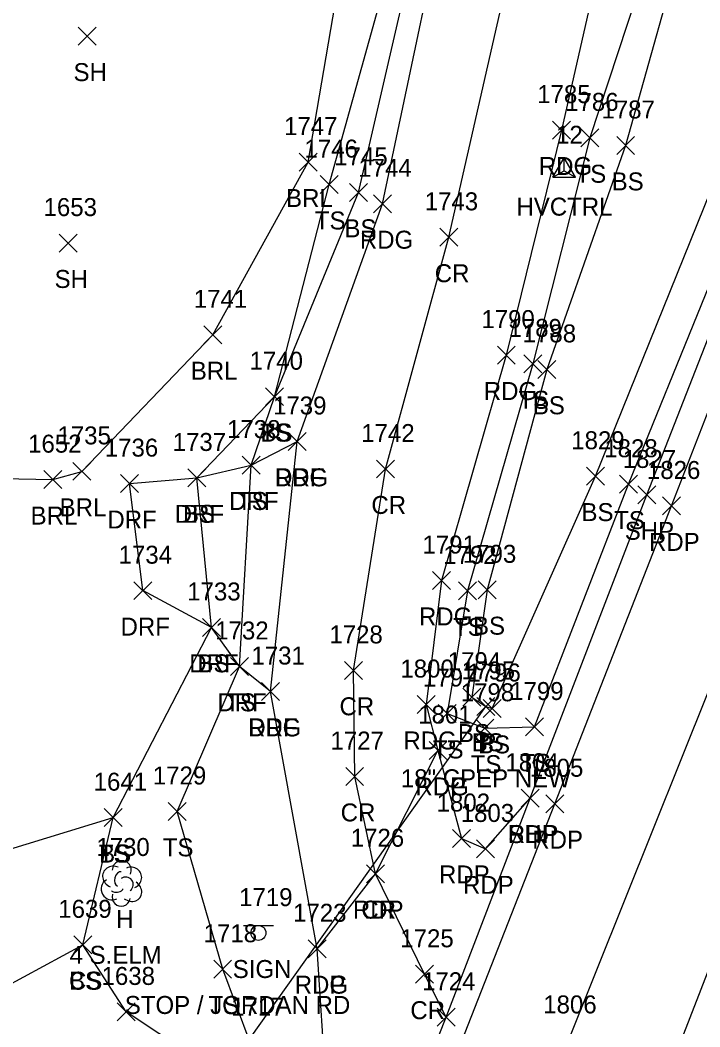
# Model space of a CAD drawing. Extents: x 1554917 to 1555870, y 813367 to 816333.
# Drawn here: x 1555214.2 to 1555289.9, y 814161.6 to 814273.6 of the extents above; entities that cross this region are included whole.
import ezdxf

# ---------------------------------------------------------------- set-up
doc = ezdxf.new("R2010")
doc.units = 0
for name, color, linetype in [('C_A', 7, 'Continuous'), ('C_I', 7, 'Continuous'), ('CPSM', 7, 'Continuous'), ('D_A', 7, 'Continuous'), ('D_C', 7, 'Continuous'), ('D_I', 7, 'Continuous'), ('D_TIC', 7, 'Continuous'), ('DCP', 7, 'Continuous'), ('L_A', 7, 'Continuous'), ('L_C', 7, 'Continuous'), ('L_I', 7, 'Continuous'), ('L_TIC', 7, 'Continuous'), ('LABL', 7, 'Continuous'), ('LELB', 7, 'Continuous'), ('LTD', 7, 'Continuous'), ('P_A', 7, 'Continuous'), ('P_I', 7, 'Continuous'), ('P_TIC', 7, 'Continuous'), ('PET', 7, 'Continuous'), ('PEU', 7, 'Continuous'), ('PRC', 7, 'Continuous'), ('PSP', 7, 'Continuous'), ('R_A', 7, 'Continuous'), ('R_I', 7, 'Continuous'), ('R_TIC', 7, 'Continuous'), ('RDF', 7, 'Continuous'), ('S_A', 7, 'Continuous'), ('S_C', 7, 'Continuous'), ('S_I', 7, 'Continuous'), ('SSGN', 7, 'Continuous')]:
    doc.layers.add(name, color=color, linetype=linetype)

msp = doc.modelspace()

# ---------------------------------------------------------------- linework, layer by layer
at = {"layer": 'CPSM'}
for p, q in [((1555273.51, 814256.16), (1555274.76, 814258.33)), ((1555276.01, 814256.16), (1555274.76, 814258.33)), ((1555274.76, 814256.88), (1555274.76, 814258.33)), ((1555273.51, 814256.16), (1555274.76, 814256.88)), ((1555274.76, 814256.88), (1555274.76, 814256.88)), ((1555274.76, 814256.88), (1555276.01, 814256.16)), ((1555273.51, 814256.16), (1555276.01, 814256.16))]:
    msp.add_line(p, q, dxfattribs=at)
at = {"layer": 'D_TIC'}
for points in [[(1555265.03, 814196.26), (1555267.03, 814198.26)], [(1555267.03, 814196.26), (1555265.03, 814198.26)]]:
    msp.add_lwpolyline(points, dxfattribs=at)
at = {"layer": 'DCP'}
msp.add_lwpolyline([(1555236.77, 814156.09), (1555266.03, 814197.26)], dxfattribs=at)
at = {"layer": 'L_TIC'}
for points in [[(1555220.63, 814270.85), (1555222.63, 814272.85)], [(1555222.63, 814270.85), (1555220.63, 814272.85)], [(1555276.62, 814259.54), (1555278.62, 814261.54)], [(1555278.62, 814259.54), (1555276.62, 814261.54)], [(1555280.61, 814258.69), (1555282.61, 814260.69)], [(1555282.61, 814258.69), (1555280.61, 814260.69)], [(1555245.25, 814256.84), (1555247.25, 814258.84)], [(1555247.25, 814256.84), (1555245.25, 814258.84)], [(1555247.59, 814254.34), (1555249.59, 814256.34)], [(1555249.59, 814254.34), (1555247.59, 814256.34)], [(1555250.85, 814253.47), (1555252.85, 814255.47)], [(1555252.85, 814253.47), (1555250.85, 814255.47)], [(1555218.52, 814247.83), (1555220.52, 814249.83)], [(1555220.52, 814247.83), (1555218.52, 814249.83)], [(1555234.64, 814237.62), (1555236.64, 814239.62)], [(1555236.64, 814237.62), (1555234.64, 814239.62)], [(1555270.26, 814234.38), (1555272.26, 814236.38)], [(1555272.26, 814234.38), (1555270.26, 814236.38)], [(1555271.83, 814233.77), (1555273.83, 814235.77)], [(1555273.83, 814233.77), (1555271.83, 814235.77)], [(1555241.5, 814230.73), (1555243.5, 814232.73)], [(1555243.5, 814230.73), (1555241.5, 814232.73)], [(1555241.5, 814230.73), (1555243.5, 814232.73)], [(1555243.5, 814230.73), (1555241.5, 814232.73)], [(1555238.91, 814223.12), (1555240.91, 814225.12)], [(1555240.91, 814223.12), (1555238.91, 814225.12)], [(1555220.03, 814222.42), (1555222.03, 814224.42)], [(1555222.03, 814222.42), (1555220.03, 814224.42)], [(1555277.25, 814221.88), (1555279.25, 814223.88)], [(1555279.25, 814221.88), (1555277.25, 814223.88)], [(1555216.8, 814221.5), (1555218.8, 814223.5)], [(1555218.8, 814221.5), (1555216.8, 814223.5)], [(1555232.86, 814221.69), (1555234.86, 814223.69)], [(1555234.86, 814221.69), (1555232.86, 814223.69)], [(1555280.92, 814220.99), (1555282.92, 814222.99)], [(1555282.92, 814220.99), (1555280.92, 814222.99)], [(1555262.98, 814209.11), (1555264.98, 814211.11)], [(1555264.98, 814209.11), (1555262.98, 814211.11)], [(1555265.17, 814209.24), (1555267.17, 814211.24)], [(1555267.17, 814209.24), (1555265.17, 814211.24)], [(1555234.48, 814205.05), (1555236.48, 814207.05)], [(1555236.48, 814205.05), (1555234.48, 814207.05)], [(1555237.6, 814200.71), (1555239.6, 814202.71)], [(1555239.6, 814200.71), (1555237.6, 814202.71)], [(1555263.49, 814197.29), (1555265.49, 814199.29)], [(1555265.49, 814197.29), (1555263.49, 814199.29)], [(1555265.03, 814196.26), (1555267.03, 814198.26)], [(1555267.03, 814196.26), (1555265.03, 814198.26)], [(1555260.73, 814195.47), (1555262.73, 814197.47)], [(1555262.73, 814195.47), (1555260.73, 814197.47)], [(1555265.73, 814196.03), (1555267.73, 814198.03)], [(1555267.73, 814196.03), (1555265.73, 814198.03)], [(1555270.45, 814193.97), (1555272.45, 814195.97)], [(1555272.45, 814193.97), (1555270.45, 814195.97)], [(1555264.94, 814193.83), (1555266.94, 814195.83)], [(1555266.94, 814193.83), (1555264.94, 814195.83)], [(1555223.53, 814183.88), (1555225.53, 814185.88)], [(1555225.53, 814183.88), (1555223.53, 814185.88)], [(1555223.53, 814183.88), (1555225.53, 814185.88)], [(1555225.53, 814183.88), (1555223.53, 814185.88)], [(1555230.65, 814184.57), (1555232.65, 814186.57)], [(1555232.65, 814184.57), (1555230.65, 814186.57)], [(1555220.17, 814169.73), (1555222.17, 814171.73)], [(1555222.17, 814169.73), (1555220.17, 814171.73)], [(1555220.17, 814169.73), (1555222.17, 814171.73)], [(1555222.17, 814169.73), (1555220.17, 814171.73)], [(1555235.73, 814167.01), (1555237.73, 814169.01)], [(1555237.73, 814167.01), (1555235.73, 814169.01)], [(1555224.98, 814162.26), (1555226.98, 814164.26)], [(1555226.98, 814162.26), (1555224.98, 814164.26)]]:
    msp.add_lwpolyline(points, dxfattribs=at)
at = {"layer": 'LABL'}
msp.add_lwpolyline([(1555170.56, 814225.07), (1555196.9, 814222.93), (1555217.8, 814222.5), (1555221.03, 814223.42), (1555235.64, 814238.62), (1555246.25, 814257.84), (1555251.52, 814288.71), (1555259.39, 814330.22), (1555249.41, 814332.16)], dxfattribs=at)
at = {"layer": 'LELB'}
for points in [[(1555296.24, 814366.8), (1555290.72, 814331.05), (1555289.09, 814310.79), (1555285.93, 814285.82), (1555277.62, 814260.54), (1555271.26, 814235.38), (1555263.98, 814210.11), (1555261.73, 814196.47), (1555265.94, 814194.83), (1555271.45, 814194.97), (1555281.92, 814221.99), (1555299.07, 814264.14), (1555315.35, 814304.52), (1555325.95, 814332.17)], [(1555236.77, 814156.09), (1555225.98, 814163.26), (1555221.17, 814170.73), (1555224.53, 814184.88), (1555235.48, 814206.05), (1555233.86, 814222.69), (1555242.5, 814231.73), (1555251.85, 814254.47), (1555261.04, 814294.17), (1555268.16, 814328.27), (1555269.68, 814335.29), (1555272.72, 814341.69)], [(1555161.57, 813925.65), (1555168.92, 813938.89), (1555173.57, 813945.95), (1555174.16, 813952.01), (1555182.4, 813974.26), (1555190.04, 813992.11), (1555201.74, 814019.14), (1555212.19, 814045.46), (1555215.96, 814054.45), (1555221.93, 814072.78), (1555233.01, 814105.58), (1555244.12, 814126.91), (1555239.17, 814141.42), (1555241.48, 814149.75), (1555239.8, 814159.84), (1555236.73, 814168.01), (1555231.65, 814185.57), (1555238.6, 814201.71), (1555239.91, 814224.12), (1555242.5, 814231.73), (1555248.59, 814255.34), (1555259.33, 814293.88), (1555265.42, 814329.58), (1555267.14, 814335.72)], [(1555288.75, 814285.24), (1555281.61, 814259.69), (1555272.83, 814234.77), (1555266.17, 814210.24), (1555264.49, 814198.29), (1555266.03, 814197.26), (1555266.73, 814197.03), (1555278.25, 814222.88), (1555295.68, 814265.95), (1555300.44, 814279.31)], [(1555172.7, 814171.33), (1555195.77, 814173.65), (1555207.42, 814179.65), (1555224.53, 814184.88)], [(1555103.83, 814081.29), (1555127.34, 814087.63), (1555145.8, 814111.67), (1555155.27, 814142.44), (1555178.24, 814154.02), (1555199.22, 814158.86), (1555221.17, 814170.73)]]:
    msp.add_lwpolyline(points, dxfattribs=at)
at = {"layer": 'LTD'}
msp.add_line((1555225.44, 814177.61), (1555225.44, 814177.61), dxfattribs=at)
msp.add_line((1555225.44, 814177.61), (1555225.44, 814177.61), dxfattribs=at)
msp.add_arc((1555225.49, 814179.04), 1.05, 335.5272, 180.9563, dxfattribs=at)
for centre, major_axis, ratio, start_param, end_param in [((1555224.65, 814178.27), (1.21, -0.51), 0.895232, 1.570796, 4.712389), ((1555226.48, 814178.19), (-1.14, -0.48), 0.949671, 1.570796, 4.712389), ((1555224.36, 814176.9), (0.58, -1.04), 0.959034, 3.141593, 6.283185), ((1555225.23, 814178.06), (-0.208, -0.792), 0.645439, 3.141593, 6.283185), ((1555225.94, 814177.44), (-0.5, 0.667), 0.989748, 3.141593, 6.283185), ((1555224.98, 814176.86), (-0.625, -0.083), 0.423636, 0, 3.141593), ((1555226.44, 814176.77), (-1.09, 0.79), 0.841452, 1.570796, 4.712389), ((1555225.44, 814176.11), (0.26, 1.06), 0.942809, 1.570796, 4.712389)]:
    msp.add_ellipse(centre, major_axis=major_axis, ratio=ratio, start_param=start_param, end_param=end_param, dxfattribs=at)
at = {"layer": 'P_TIC'}
for points in [[(1555273.45, 814260.4), (1555275.45, 814262.4)], [(1555275.45, 814260.4), (1555273.45, 814262.4)], [(1555253.52, 814252.2), (1555255.52, 814254.2)], [(1555255.52, 814252.2), (1555253.52, 814254.2)], [(1555260.92, 814248.47), (1555262.92, 814250.47)], [(1555262.92, 814248.47), (1555260.92, 814250.47)], [(1555267.32, 814235.36), (1555269.32, 814237.36)], [(1555269.32, 814235.36), (1555267.32, 814237.36)], [(1555244.04, 814225.75), (1555246.04, 814227.75)], [(1555246.04, 814225.75), (1555244.04, 814227.75)], [(1555253.86, 814222.68), (1555255.86, 814224.68)], [(1555255.86, 814222.68), (1555253.86, 814224.68)], [(1555282.98, 814219.8), (1555284.98, 814221.8)], [(1555284.98, 814219.8), (1555282.98, 814221.8)], [(1555285.72, 814218.57), (1555287.72, 814220.57)], [(1555287.72, 814218.57), (1555285.72, 814220.57)], [(1555260.1, 814210.27), (1555262.1, 814212.27)], [(1555262.1, 814210.27), (1555260.1, 814212.27)], [(1555250.3, 814200.27), (1555252.3, 814202.27)], [(1555252.3, 814200.27), (1555250.3, 814202.27)], [(1555241.05, 814197.92), (1555243.05, 814199.92)], [(1555243.05, 814197.92), (1555241.05, 814199.92)], [(1555258.38, 814196.47), (1555260.38, 814198.47)], [(1555260.38, 814196.47), (1555258.38, 814198.47)], [(1555259.71, 814191.35), (1555261.71, 814193.35)], [(1555261.71, 814191.35), (1555259.71, 814193.35)], [(1555259.71, 814191.35), (1555261.71, 814193.35)], [(1555261.71, 814191.35), (1555259.71, 814193.35)], [(1555250.43, 814188.46), (1555252.43, 814190.46)], [(1555252.43, 814188.46), (1555250.43, 814190.46)], [(1555269.99, 814186.05), (1555271.99, 814188.05)], [(1555271.99, 814186.05), (1555269.99, 814188.05)], [(1555269.99, 814186.05), (1555271.99, 814188.05)], [(1555271.99, 814186.05), (1555269.99, 814188.05)], [(1555272.72, 814185.43), (1555274.72, 814187.43)], [(1555274.72, 814185.43), (1555272.72, 814187.43)], [(1555262.33, 814181.56), (1555264.33, 814183.56)], [(1555264.33, 814181.56), (1555262.33, 814183.56)], [(1555265.01, 814180.4), (1555267.01, 814182.4)], [(1555267.01, 814180.4), (1555265.01, 814182.4)], [(1555252.74, 814177.64), (1555254.74, 814179.64)], [(1555254.74, 814177.64), (1555252.74, 814179.64)], [(1555252.74, 814177.64), (1555254.74, 814179.64)], [(1555254.74, 814177.64), (1555252.74, 814179.64)], [(1555246.26, 814169.29), (1555248.26, 814171.29)], [(1555248.26, 814169.29), (1555246.26, 814171.29)], [(1555246.26, 814169.29), (1555248.26, 814171.29)], [(1555248.26, 814169.29), (1555246.26, 814171.29)], [(1555258.2, 814166.45), (1555260.2, 814168.45)], [(1555260.2, 814166.45), (1555258.2, 814168.45)], [(1555260.62, 814161.67), (1555262.62, 814163.67)], [(1555262.62, 814161.67), (1555260.62, 814163.67)], [(1555260.62, 814161.67), (1555262.62, 814163.67)], [(1555262.62, 814161.67), (1555260.62, 814163.67)]]:
    msp.add_lwpolyline(points, dxfattribs=at)
at = {"layer": 'PET'}
for points in [[(1555161.36, 813900.53), (1555183.5, 813956.99), (1555189.63, 813971.7), (1555196.36, 813987.75), (1555203.89, 814008), (1555206.01, 814012.95), (1555218.07, 814043.52), (1555227.32, 814068.19), (1555240.79, 814103.21), (1555254.41, 814137.22), (1555273.72, 814186.43), (1555286.72, 814219.57), (1555303.34, 814262.32), (1555319.11, 814302.56), (1555330.34, 814331.97)], [(1555182.57, 813892.25), (1555203.7, 813945.01), (1555216.85, 813978.34), (1555228.72, 814008.85), (1555239.47, 814035.47), (1555248.64, 814059.88), (1555262.92, 814096.01), (1555276.68, 814131.3), (1555286.36, 814156.33), (1555297.11, 814184.04), (1555306.67, 814209.51), (1555324.28, 814253.26), (1555340.35, 814293.54), (1555352.6, 814325.05)], [(1555248.96, 814130.73), (1555248.65, 814139.98), (1555248.27, 814154.83), (1555247.26, 814170.29), (1555253.74, 814178.64), (1555260.71, 814192.35), (1555263.33, 814182.56), (1555266.01, 814181.4), (1555270.99, 814187.05)]]:
    msp.add_lwpolyline(points, dxfattribs=at)
at = {"layer": 'PEU'}
for points in [[(1555247.26, 814170.29), (1555242.05, 814198.92), (1555245.04, 814226.75), (1555254.52, 814253.2), (1555263.19, 814294.17), (1555270.38, 814328.05), (1555270.98, 814335.52), (1555272.72, 814341.69), (1555275.54, 814362.57), (1555278.04, 814372.88)], [(1555294.23, 814367.85), (1555287.98, 814331.7), (1555283.95, 814310.99), (1555280.12, 814286.26), (1555274.45, 814261.4), (1555268.32, 814236.36), (1555261.1, 814211.27), (1555259.38, 814197.47), (1555260.71, 814192.35)]]:
    msp.add_lwpolyline(points, dxfattribs=at)
at = {"layer": 'PRC'}
for points in [[(1555261.62, 814162.67), (1555259.2, 814167.45), (1555253.74, 814178.64), (1555251.43, 814189.46), (1555251.3, 814201.27), (1555254.86, 814223.68), (1555261.92, 814249.47), (1555271.63, 814292.21), (1555278.12, 814326.56), (1555280.66, 814350.27), (1555285.82, 814371.24)], [(1554976.76, 813382.18), (1554992.84, 813427.9), (1555014.07, 813486.01), (1555030.62, 813532.31), (1555046.37, 813573.08), (1555064.69, 813621.19), (1555082.41, 813667.53), (1555112.1, 813744.1), (1555110.69, 813739.79), (1555136.16, 813805.74), (1555152.52, 813846.93), (1555172.03, 813896.18), (1555193.96, 813951.2), (1555206.37, 813983.4), (1555218.13, 814013.22), (1555228.65, 814039.26), (1555237.93, 814064.31), (1555252.22, 814099.76), (1555265.8, 814135.89), (1555275.26, 814160.09), (1555297.17, 814214.77), (1555313.83, 814257.94), (1555329.72, 814298.26), (1555342.03, 814329.92)]]:
    msp.add_lwpolyline(points, dxfattribs=at)
at = {"layer": 'PSP'}
msp.add_lwpolyline([(1555160.79, 813906.47), (1555173.05, 813937.33), (1555179.42, 813953.63), (1555181.24, 813957.84), (1555186.72, 813973.16), (1555194.02, 813990.9), (1555204.38, 814016.29), (1555205.03, 814017.75), (1555215.29, 814044.5), (1555224.66, 814068.93), (1555238.68, 814103.48), (1555248.96, 814130.73), (1555261.62, 814162.67), (1555270.99, 814187.05), (1555283.98, 814220.8), (1555300.65, 814263.34), (1555316.51, 814303.51), (1555327.36, 814331.38)], dxfattribs=at)
at = {"layer": 'R_TIC'}
for points in [[(1555244.04, 814225.75), (1555246.04, 814227.75)], [(1555246.04, 814225.75), (1555244.04, 814227.75)], [(1555238.91, 814223.12), (1555240.91, 814225.12)], [(1555240.91, 814223.12), (1555238.91, 814225.12)], [(1555225.35, 814221.06), (1555227.35, 814223.06)], [(1555227.35, 814221.06), (1555225.35, 814223.06)], [(1555232.86, 814221.69), (1555234.86, 814223.69)], [(1555234.86, 814221.69), (1555232.86, 814223.69)], [(1555226.83, 814209.14), (1555228.83, 814211.14)], [(1555228.83, 814209.14), (1555226.83, 814211.14)], [(1555234.48, 814205.05), (1555236.48, 814207.05)], [(1555236.48, 814205.05), (1555234.48, 814207.05)], [(1555237.6, 814200.71), (1555239.6, 814202.71)], [(1555239.6, 814200.71), (1555237.6, 814202.71)], [(1555241.05, 814197.92), (1555243.05, 814199.92)], [(1555243.05, 814197.92), (1555241.05, 814199.92)]]:
    msp.add_lwpolyline(points, dxfattribs=at)
at = {"layer": 'RDF'}
msp.add_lwpolyline([(1555242.05, 814198.92), (1555238.6, 814201.71), (1555235.48, 814206.05), (1555227.83, 814210.14), (1555226.35, 814222.06), (1555233.86, 814222.69), (1555239.91, 814224.12), (1555245.04, 814226.75)], dxfattribs=at)
at = {"layer": 'SSGN'}
for p, q in [((1555239.06, 814172.89), (1555242.4, 814172.89)), ((1555240.71, 814172.05), (1555240.71, 814172.05))]:
    msp.add_line(p, q, dxfattribs=at)
msp.add_circle((1555240.71, 814172.05), 0.833, dxfattribs=at)

# ---------------------------------------------------------------- texts
at = {"layer": 'C_A'}
msp.add_text('HVCTRL', height=2, dxfattribs=at).set_placement((1555269.45, 814251.88))
at = {"layer": 'C_I'}
msp.add_text('12', height=2, dxfattribs=at).set_placement((1555273.86, 814259.88))
at = {"layer": 'D_A'}
msp.add_text('P', height=2, dxfattribs=at).set_placement((1555265.41, 814192.26))
at = {"layer": 'D_C'}
msp.add_text('18" CPEP NEW', height=2, dxfattribs=at).set_placement((1555256.57, 814188.26))
at = {"layer": 'D_I'}
msp.add_text('1795', height=2, dxfattribs=at).set_placement((1555263.34, 814200.26))
at = {"layer": 'L_A'}
for s, p in [('SH', (1555220.12, 814266.85)), ('TS', (1555276.03, 814255.54)), ('BS', (1555280.05, 814254.69)), ('BRL', (1555243.79, 814252.84)), ('TS', (1555247, 814250.34)), ('BS', (1555250.29, 814249.47)), ('SH', (1555218.01, 814243.83)), ('BRL', (1555233.18, 814233.62)), ('TS', (1555269.67, 814230.38)), ('BS', (1555271.27, 814229.77)), ('TS', (1555240.91, 814226.73)), ('BS', (1555240.94, 814226.73)), ('TS', (1555238.32, 814219.12)), ('BRL', (1555215.34, 814217.5)), ('BRL', (1555218.57, 814218.42)), ('BS', (1555232.3, 814217.69)), ('BS', (1555276.69, 814217.88)), ('TS', (1555280.33, 814216.99)), ('TS', (1555262.39, 814205.11)), ('BS', (1555264.61, 814205.24)), ('BS', (1555233.92, 814201.05)), ('TS', (1555237.01, 814196.71)), ('BS', (1555262.93, 814193.29)), ('BS', (1555264.47, 814192.26)), ('BS', (1555265.17, 814192.03)), ('TS', (1555260.14, 814191.47)), ('TS', (1555264.35, 814189.83)), ('TS', (1555269.86, 814189.97)), ('TS', (1555230.06, 814180.57)), ('TS', (1555222.94, 814179.88)), ('BS', (1555222.97, 814179.88)), ('H', (1555224.87, 814172.61)), ('CS', (1555219.61, 814165.73)), ('BS', (1555219.61, 814165.73)), ('TS', (1555235.14, 814163.01))]:
    msp.add_text(s, height=2, dxfattribs=at).set_placement(p)
at = {"layer": 'L_C'}
msp.add_text('4 S.ELM', height=2, dxfattribs=at).set_placement((1555219.68, 814168.61))
at = {"layer": 'L_I'}
for s, p in [('1786', (1555274.87, 814263.54)), ('1787', (1555278.92, 814262.69)), ('1747', (1555243.56, 814260.84)), ('1746', (1555245.84, 814258.34)), ('1745', (1555249.16, 814257.47)), ('1653', (1555216.78, 814251.83)), ('1741', (1555233.51, 814241.62)), ('1789', (1555268.56, 814238.38)), ('1788', (1555270.14, 814237.77)), ('1740', (1555239.72, 814234.73)), ('1740', (1555239.72, 814234.73)), ('1735', (1555218.33, 814226.42)), ('1738', (1555237.22, 814227.12)), ('1652', (1555215.06, 814225.5)), ('1737', (1555231.16, 814225.69)), ('1829', (1555275.55, 814225.88)), ('1828', (1555279.23, 814224.99)), ('1792', (1555261.29, 814213.11)), ('1793', (1555263.48, 814213.24)), ('1733', (1555232.78, 814209.05)), ('1732', (1555235.9, 814204.71)), ('1794', (1555261.79, 814201.29)), ('1797', (1555259.04, 814199.47)), ('1795', (1555263.34, 814200.26)), ('1796', (1555263.98, 814200.03)), ('1798', (1555263.24, 814197.83)), ('1799', (1555268.75, 814197.97)), ('1729', (1555228.95, 814188.57)), ('1641', (1555222.36, 814187.88)), ('1641', (1555222.36, 814187.88)), ('1730', (1555222.66, 814180.61)), ('1639', (1555218.42, 814173.73)), ('1639', (1555218.42, 814173.73)), ('1718', (1555234.61, 814171.01)), ('1638', (1555223.24, 814166.26)), ('1717', (1555237.67, 814162.84))]:
    msp.add_text(s, height=2, dxfattribs=at).set_placement(p)
at = {"layer": 'P_A'}
for s, p in [('RDG', (1555271.94, 814256.4)), ('RDG', (1555252.01, 814248.2)), ('CR', (1555260.35, 814244.47)), ('RDG', (1555265.81, 814231.36)), ('RDG', (1555242.53, 814221.75)), ('CR', (1555253.29, 814218.68)), ('SHP', (1555281.51, 814215.8)), ('RDP', (1555284.21, 814214.57)), ('RDG', (1555258.59, 814206.27)), ('CR', (1555249.74, 814196.27)), ('RDG', (1555239.54, 814193.92)), ('RDG', (1555256.86, 814192.47)), ('RDG', (1555258.2, 814187.35)), ('RDP', (1555258.2, 814187.35)), ('CR', (1555249.87, 814184.46)), ('SHP', (1555268.53, 814182.05)), ('RDP', (1555268.48, 814182.05)), ('RDP', (1555271.21, 814181.43)), ('RDP', (1555260.82, 814177.56)), ('RDP', (1555263.5, 814176.4)), ('CR', (1555252.17, 814173.64)), ('RDP', (1555251.23, 814173.64)), ('RDG', (1555244.75, 814165.29)), ('RDP', (1555244.75, 814165.29)), ('CR', (1555257.63, 814162.45))]:
    msp.add_text(s, height=2, dxfattribs=at).set_placement(p)
at = {"layer": 'P_I'}
for s, p in [('1785', (1555271.76, 814264.4)), ('1744', (1555251.83, 814256.2)), ('1743', (1555259.23, 814252.47)), ('1790', (1555265.54, 814239.36)), ('1739', (1555242.34, 814229.75)), ('1742', (1555252.16, 814226.68)), ('1827', (1555281.28, 814223.8)), ('1826', (1555283.98, 814222.57)), ('1791', (1555258.98, 814214.27)), ('1728', (1555248.61, 814204.27)), ('1731', (1555239.93, 814201.92)), ('1800', (1555256.52, 814200.47)), ('1801', (1555258.51, 814195.35)), ('1801', (1555258.51, 814195.35)), ('1727', (1555248.74, 814192.46)), ('1804', (1555268.22, 814190.05)), ('1804', (1555268.22, 814190.05)), ('1805', (1555270.95, 814189.43)), ('1802', (1555260.56, 814185.56)), ('1803', (1555263.24, 814184.4)), ('1726', (1555250.99, 814181.64)), ('1726', (1555250.99, 814181.64)), ('1723', (1555244.57, 814173.29)), ('1723', (1555244.57, 814173.29)), ('1725', (1555256.51, 814170.45)), ('1724', (1555258.93, 814165.67)), ('1724', (1555258.93, 814165.67)), ('1806', (1555272.43, 814163.09))]:
    msp.add_text(s, height=2, dxfattribs=at).set_placement(p)
at = {"layer": 'R_A'}
for p in [(1555242.57, 814221.75), (1555237.45, 814219.12), (1555231.39, 814217.69), (1555223.89, 814217.06), (1555225.36, 814205.14), (1555233.01, 814201.05), (1555236.13, 814196.71), (1555239.59, 814193.92)]:
    msp.add_text('DRF', height=2, dxfattribs=at).set_placement(p)
at = {"layer": 'R_I'}
for s, p in [('1739', (1555242.34, 814229.75)), ('1738', (1555237.22, 814227.12)), ('1737', (1555231.16, 814225.69)), ('1736', (1555223.6, 814225.06)), ('1734', (1555225.14, 814213.14)), ('1733', (1555232.78, 814209.05)), ('1732', (1555235.9, 814204.71)), ('1731', (1555239.93, 814201.92))]:
    msp.add_text(s, height=2, dxfattribs=at).set_placement(p)
at = {"layer": 'S_A'}
msp.add_text('SIGN', height=2, dxfattribs=at).set_placement((1555237.85, 814167.03))
at = {"layer": 'S_C'}
msp.add_text('STOP / JORDAN RD', height=2, dxfattribs=at).set_placement((1555225.83, 814163.03))
at = {"layer": 'S_I'}
msp.add_text('1719', height=2, dxfattribs=at).set_placement((1555238.56, 814175.03))

doc.saveas('drawing.dxf')
